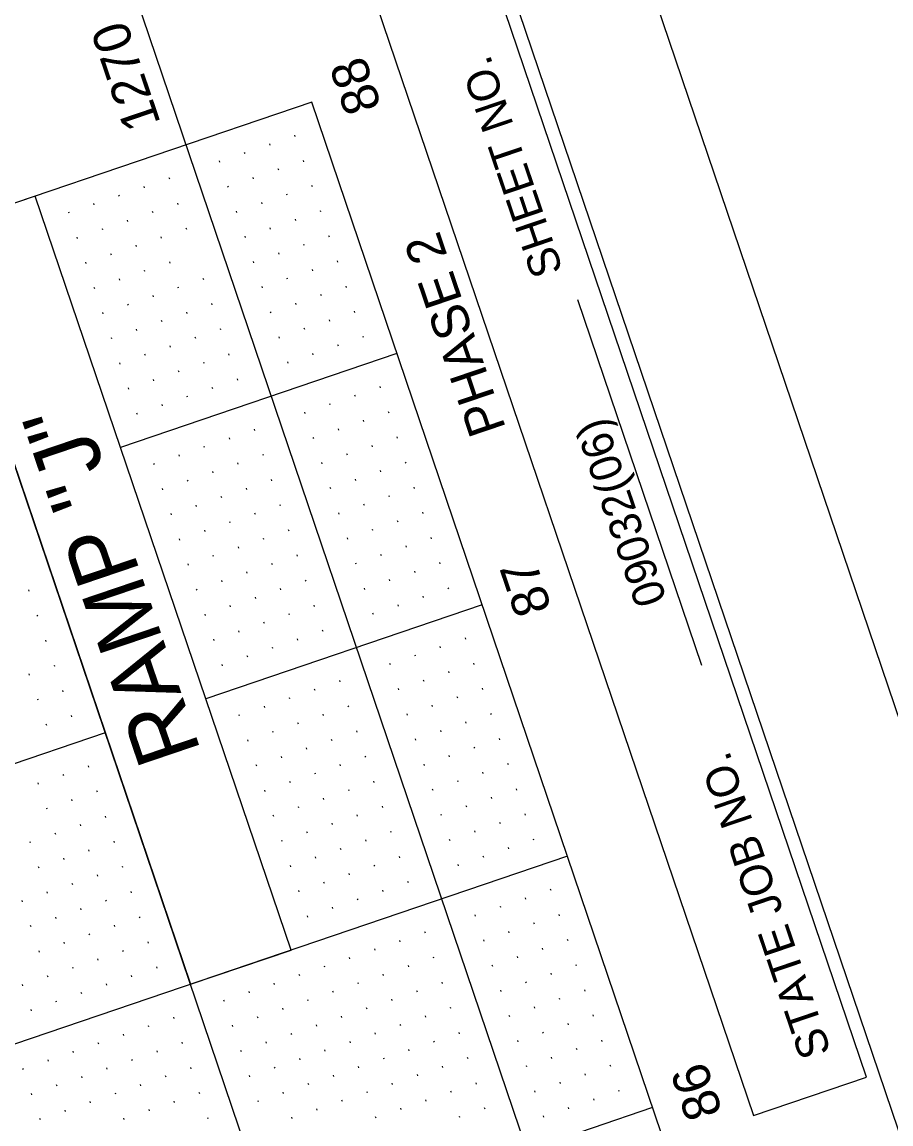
# Model space of a CAD drawing. Extents: x 2150800 to 2152547, y 141860 to 143950.
# Drawn here: x 2151789.3 to 2151953.1, y 143638.5 to 143846.1 of the extents above; entities that cross this region are included whole.
import ezdxf

# ---------------------------------------------------------------- set-up
doc = ezdxf.new("R2010")
doc.units = 0
for name, color, linetype in [('PR_Align_Ramp_J_Sta', 7, 'Continuous'), ('SHT_Plan_Profile_Sheet_Elev_Txt', 7, 'Continuous'), ('SHT_Plan_Profile_Sheet_Sta_Txt', 7, 'Continuous'), ('SHT_Plan_Profile_Sheet_Txt', 7, 'Continuous'), ('SHT_Plot_Shape_Half', 7, 'Continuous'), ('SHT_Profile_Grid_Major', 7, 'Continuous'), ('SHT_Profile_Grid_Minor', 7, 'Continuous'), ('SHT_Sheet_Border', 7, 'Continuous'), ('SHT_Standard_Sheet_Lines', 7, 'Continuous')]:
    doc.layers.add(name, color=color, linetype=linetype)

msp = doc.modelspace()

# ---------------------------------------------------------------- linework, layer by layer
at = {"layer": 'SHT_Plot_Shape_Half'}
msp.add_lwpolyline([(2151391.39, 141950.92), (2150845.24, 143560.8), (2151886.93, 143914.19), (2152433.08, 142304.31)], close=True, dxfattribs=at)
at = {"layer": 'SHT_Profile_Grid_Major'}
for p, q in [((2152314.16, 142366.92), (2151808.17, 143858.43)), ((2152266.81, 142350.86), (2151760.82, 143842.37)), ((2151859.95, 143783.6), (2151807.87, 143765.93)), ((2151876.02, 143736.25), (2151823.93, 143718.58)), ((2151804.99, 143712.16), (2151468.81, 143598.11)), ((2151892.08, 143688.9), (2151484.88, 143550.76)), ((2151908.14, 143641.55), (2151458.32, 143488.95))]:
    msp.add_line(p, q, dxfattribs=at)
at = {"layer": 'SHT_Profile_Grid_Minor'}
for p, q in [((2151840.8, 143824.49), (2151840.72, 143824.73)), ((2151836.07, 143822.88), (2151835.99, 143823.12)), ((2151831.33, 143821.28), (2151831.25, 143821.52)), ((2151826.6, 143819.67), (2151826.52, 143819.91)), ((2151842.41, 143819.76), (2151842.33, 143819.99)), ((2151817.13, 143816.46), (2151817.05, 143816.7)), ((2151832.94, 143816.54), (2151832.86, 143816.78)), ((2151837.67, 143818.15), (2151837.59, 143818.39)), ((2151812.39, 143814.85), (2151812.31, 143815.09)), ((2151828.2, 143814.94), (2151828.12, 143815.17)), ((2151844.02, 143815.02), (2151843.94, 143815.26)), ((2151807.66, 143813.25), (2151807.58, 143813.48)), ((2151839.28, 143813.42), (2151839.2, 143813.65)), ((2151798.19, 143810.03), (2151798.11, 143810.27)), ((2151802.92, 143811.64), (2151802.84, 143811.88)), ((2151814, 143810.12), (2151813.92, 143810.36)), ((2151818.73, 143811.72), (2151818.65, 143811.96)), ((2151829.81, 143810.2), (2151829.73, 143810.44)), ((2151834.55, 143811.81), (2151834.47, 143812.05)), ((2151845.62, 143810.29), (2151845.54, 143810.52)), ((2151809.26, 143808.51), (2151809.18, 143808.75)), ((2151840.89, 143808.68), (2151840.81, 143808.92)), ((2151804.53, 143806.91), (2151804.45, 143807.14)), ((2151820.34, 143806.99), (2151820.26, 143807.23)), ((2151836.15, 143807.07), (2151836.07, 143807.31)), ((2151799.79, 143805.3), (2151799.71, 143805.54)), ((2151810.87, 143803.78), (2151810.79, 143804.01)), ((2151815.61, 143805.38), (2151815.53, 143805.62)), ((2151831.42, 143805.47), (2151831.34, 143805.7)), ((2151842.49, 143803.95), (2151842.41, 143804.18)), ((2151847.23, 143805.55), (2151847.15, 143805.79)), ((2151806.14, 143802.17), (2151806.06, 143802.41)), ((2151837.76, 143802.34), (2151837.68, 143802.58)), ((2151801.4, 143800.56), (2151801.32, 143800.8)), ((2151817.21, 143800.65), (2151817.13, 143800.89)), ((2151833.02, 143800.73), (2151832.94, 143800.97)), ((2151848.83, 143800.82), (2151848.75, 143801.05)), ((2151812.48, 143799.04), (2151812.4, 143799.28)), ((2151823.55, 143797.52), (2151823.47, 143797.76)), ((2151839.36, 143797.6), (2151839.28, 143797.84)), ((2151844.1, 143799.21), (2151844.02, 143799.45)), ((2151803.01, 143795.83), (2151802.93, 143796.07)), ((2151807.74, 143797.44), (2151807.66, 143797.67)), ((2151818.82, 143795.91), (2151818.74, 143796.15)), ((2151834.63, 143796), (2151834.55, 143796.23)), ((2151850.44, 143796.08), (2151850.36, 143796.32)), ((2151814.08, 143794.31), (2151814, 143794.54)), ((2151845.71, 143794.48), (2151845.63, 143794.71)), ((2151809.35, 143792.7), (2151809.27, 143792.94)), ((2151825.16, 143792.78), (2151825.08, 143793.02)), ((2151836.24, 143791.26), (2151836.16, 143791.5)), ((2151840.97, 143792.87), (2151840.89, 143793.11)), ((2151852.05, 143791.35), (2151851.97, 143791.58)), ((2151804.61, 143791.09), (2151804.53, 143791.33)), ((2151815.69, 143789.57), (2151815.61, 143789.81)), ((2151820.42, 143791.18), (2151820.34, 143791.42)), ((2151847.31, 143789.74), (2151847.23, 143789.98)), ((2151810.96, 143787.97), (2151810.87, 143788.2)), ((2151826.77, 143788.05), (2151826.69, 143788.29)), ((2151842.58, 143788.13), (2151842.5, 143788.37)), ((2151806.22, 143786.36), (2151806.14, 143786.6)), ((2151822.03, 143786.44), (2151821.95, 143786.68)), ((2151837.84, 143786.53), (2151837.76, 143786.76)), ((2151853.65, 143786.61), (2151853.57, 143786.85)), ((2151812.56, 143783.23), (2151812.48, 143783.47)), ((2151817.3, 143784.84), (2151817.22, 143785.07)), ((2151828.37, 143783.32), (2151828.29, 143783.55)), ((2151844.18, 143783.4), (2151844.1, 143783.64)), ((2151848.92, 143785.01), (2151848.84, 143785.24)), ((2151807.83, 143781.62), (2151807.75, 143781.86)), ((2151823.64, 143781.71), (2151823.56, 143781.95)), ((2151839.45, 143781.79), (2151839.37, 143782.03)), ((2151818.9, 143780.1), (2151818.82, 143780.34)), ((2151809.43, 143776.89), (2151809.35, 143777.13)), ((2151814.17, 143778.5), (2151814.09, 143778.73)), ((2151825.24, 143776.97), (2151825.16, 143777.21)), ((2151829.98, 143778.58), (2151829.9, 143778.82)), ((2151856.87, 143777.14), (2151856.79, 143777.38)), ((2151820.51, 143775.37), (2151820.43, 143775.6)), ((2151852.13, 143775.54), (2151852.05, 143775.77)), ((2151815.77, 143773.76), (2151815.69, 143774)), ((2151847.4, 143773.93), (2151847.32, 143774.17)), ((2151811.04, 143772.15), (2151810.96, 143772.39)), ((2151842.66, 143772.32), (2151842.58, 143772.56)), ((2151853.74, 143770.8), (2151853.66, 143771.04)), ((2151858.47, 143772.41), (2151858.39, 143772.64)), ((2151833.19, 143769.11), (2151833.11, 143769.35)), ((2151849, 143769.19), (2151848.92, 143769.43)), ((2151828.46, 143767.5), (2151828.38, 143767.74)), ((2151844.27, 143767.59), (2151844.19, 143767.82)), ((2151860.08, 143767.67), (2151860, 143767.91)), ((2151818.99, 143764.29), (2151818.91, 143764.53)), ((2151823.72, 143765.9), (2151823.64, 143766.13)), ((2151834.8, 143764.38), (2151834.72, 143764.61)), ((2151850.61, 143764.46), (2151850.53, 143764.7)), ((2151855.34, 143766.07), (2151855.26, 143766.3)), ((2151814.25, 143762.68), (2151814.17, 143762.92)), ((2151830.06, 143762.77), (2151829.98, 143763.01)), ((2151845.87, 143762.85), (2151845.79, 143763.09)), ((2151861.69, 143762.94), (2151861.6, 143763.17)), ((2151825.33, 143761.16), (2151825.25, 143761.4)), ((2151856.95, 143761.33), (2151856.87, 143761.57)), ((2151820.59, 143759.56), (2151820.51, 143759.79)), ((2151836.4, 143759.64), (2151836.32, 143759.88)), ((2151847.48, 143758.12), (2151847.4, 143758.35)), ((2151852.22, 143759.72), (2151852.13, 143759.96)), ((2151863.29, 143758.2), (2151863.21, 143758.44)), ((2151815.86, 143757.95), (2151815.78, 143758.19)), ((2151826.93, 143756.43), (2151826.85, 143756.66)), ((2151831.67, 143758.03), (2151831.59, 143758.27)), ((2151858.56, 143756.6), (2151858.48, 143756.83)), ((2151822.2, 143754.82), (2151822.12, 143755.06)), ((2151838.01, 143754.91), (2151837.93, 143755.14)), ((2151853.82, 143754.99), (2151853.74, 143755.23)), ((2151817.46, 143753.22), (2151817.38, 143753.45)), ((2151833.28, 143753.3), (2151833.2, 143753.54)), ((2151849.09, 143753.38), (2151849.01, 143753.62)), ((2151860.16, 143751.86), (2151860.08, 143752.1)), ((2151864.9, 143753.47), (2151864.82, 143753.7)), ((2151823.81, 143750.09), (2151823.73, 143750.32)), ((2151828.54, 143751.69), (2151828.46, 143751.93)), ((2151839.62, 143750.17), (2151839.54, 143750.41)), ((2151855.43, 143750.25), (2151855.35, 143750.49)), ((2151819.07, 143748.48), (2151818.99, 143748.72)), ((2151834.88, 143748.56), (2151834.8, 143748.8)), ((2151850.69, 143748.65), (2151850.61, 143748.88)), ((2151866.5, 143748.73), (2151866.42, 143748.97)), ((2151830.15, 143746.96), (2151830.07, 143747.19)), ((2151861.77, 143747.13), (2151861.69, 143747.36)), ((2151820.68, 143743.75), (2151820.6, 143743.98)), ((2151825.41, 143745.35), (2151825.33, 143745.59)), ((2151836.49, 143743.83), (2151836.41, 143744.07)), ((2151841.22, 143745.44), (2151841.14, 143745.67)), ((2151852.3, 143743.91), (2151852.22, 143744.15)), ((2151857.03, 143745.52), (2151856.95, 143745.76)), ((2151868.11, 143744), (2151868.03, 143744.23)), ((2151831.75, 143742.22), (2151831.67, 143742.46)), ((2151863.38, 143742.39), (2151863.3, 143742.63)), ((2151827.02, 143740.62), (2151826.94, 143740.85)), ((2151842.83, 143740.7), (2151842.75, 143740.94)), ((2151858.64, 143740.78), (2151858.56, 143741.02)), ((2151790.66, 143738.84), (2151790.58, 143739.08)), ((2151822.28, 143739.01), (2151822.2, 143739.25)), ((2151833.36, 143737.49), (2151833.28, 143737.72)), ((2151838.09, 143739.09), (2151838.01, 143739.33)), ((2151853.91, 143739.18), (2151853.83, 143739.41)), ((2151864.98, 143737.66), (2151864.9, 143737.89)), ((2151869.72, 143739.26), (2151869.64, 143739.5)), ((2151828.62, 143735.88), (2151828.54, 143736.12)), ((2151844.44, 143735.97), (2151844.36, 143736.2)), ((2151860.25, 143736.05), (2151860.17, 143736.29)), ((2151792.27, 143734.11), (2151792.19, 143734.34)), ((2151823.89, 143734.28), (2151823.81, 143734.51)), ((2151839.7, 143734.36), (2151839.62, 143734.6)), ((2151855.51, 143734.44), (2151855.43, 143734.68)), ((2151830.23, 143731.15), (2151830.15, 143731.38)), ((2151834.97, 143732.75), (2151834.89, 143732.99)), ((2151846.04, 143731.23), (2151845.96, 143731.47)), ((2151793.87, 143729.37), (2151793.79, 143729.61)), ((2151825.5, 143729.54), (2151825.42, 143729.78)), ((2151841.31, 143729.62), (2151841.23, 143729.86)), ((2151872.93, 143729.79), (2151872.85, 143730.03)), ((2151836.57, 143728.02), (2151836.49, 143728.25)), ((2151868.19, 143728.19), (2151868.11, 143728.42)), ((2151831.84, 143726.41), (2151831.76, 143726.65)), ((2151858.72, 143724.97), (2151858.64, 143725.21)), ((2151863.46, 143726.58), (2151863.38, 143726.82)), ((2151874.54, 143725.06), (2151874.46, 143725.29)), ((2151790.74, 143723.03), (2151790.66, 143723.27)), ((2151795.48, 143724.64), (2151795.4, 143724.87)), ((2151827.1, 143724.81), (2151827.02, 143725.04)), ((2151869.8, 143723.45), (2151869.72, 143723.69)), ((2151849.25, 143721.76), (2151849.17, 143722)), ((2151865.07, 143721.84), (2151864.99, 143722.08)), ((2151797.09, 143719.9), (2151797.01, 143720.14)), ((2151844.52, 143720.15), (2151844.44, 143720.39)), ((2151860.33, 143720.24), (2151860.25, 143720.48)), ((2151871.41, 143718.72), (2151871.33, 143718.95)), ((2151876.14, 143720.32), (2151876.06, 143720.56)), ((2151792.35, 143718.3), (2151792.27, 143718.53)), ((2151835.05, 143716.94), (2151834.97, 143717.18)), ((2151839.78, 143718.55), (2151839.7, 143718.78)), ((2151850.86, 143717.03), (2151850.78, 143717.26)), ((2151866.67, 143717.11), (2151866.59, 143717.35)), ((2151798.69, 143715.17), (2151798.61, 143715.4)), ((2151830.31, 143715.34), (2151830.23, 143715.57)), ((2151846.13, 143715.42), (2151846.05, 143715.66)), ((2151861.94, 143715.5), (2151861.86, 143715.74)), ((2151877.75, 143715.59), (2151877.67, 143715.82)), ((2151793.96, 143713.56), (2151793.88, 143713.8)), ((2151841.39, 143713.81), (2151841.31, 143714.05)), ((2151868.28, 143712.37), (2151868.2, 143712.61)), ((2151873.01, 143713.98), (2151872.93, 143714.22)), ((2151831.92, 143710.6), (2151831.84, 143710.84)), ((2151836.66, 143712.21), (2151836.58, 143712.44)), ((2151847.73, 143710.68), (2151847.65, 143710.92)), ((2151852.47, 143712.29), (2151852.39, 143712.53)), ((2151863.54, 143710.77), (2151863.46, 143711.01)), ((2151879.35, 143710.85), (2151879.27, 143711.09)), ((2151843, 143709.08), (2151842.92, 143709.31)), ((2151874.62, 143709.25), (2151874.54, 143709.48)), ((2151838.26, 143707.47), (2151838.18, 143707.71)), ((2151854.07, 143707.56), (2151853.99, 143707.79)), ((2151869.88, 143707.64), (2151869.8, 143707.88)), ((2151797.17, 143704.09), (2151797.09, 143704.33)), ((2151801.91, 143705.7), (2151801.82, 143705.93)), ((2151833.53, 143705.87), (2151833.45, 143706.1)), ((2151844.6, 143704.34), (2151844.52, 143704.58)), ((2151849.34, 143705.95), (2151849.26, 143706.19)), ((2151865.15, 143706.03), (2151865.07, 143706.27)), ((2151876.23, 143704.51), (2151876.15, 143704.75)), ((2151880.96, 143706.12), (2151880.88, 143706.35)), ((2151792.44, 143702.48), (2151792.35, 143702.72)), ((2151839.87, 143702.74), (2151839.79, 143702.97)), ((2151855.68, 143702.82), (2151855.6, 143703.06)), ((2151871.49, 143702.9), (2151871.41, 143703.14)), ((2151803.51, 143700.96), (2151803.43, 143701.2)), ((2151835.13, 143701.13), (2151835.05, 143701.37)), ((2151850.94, 143701.21), (2151850.86, 143701.45)), ((2151866.76, 143701.3), (2151866.68, 143701.54)), ((2151882.57, 143701.38), (2151882.49, 143701.62)), ((2151798.78, 143699.36), (2151798.7, 143699.59)), ((2151841.48, 143698), (2151841.39, 143698.24)), ((2151846.21, 143699.61), (2151846.13, 143699.85)), ((2151857.29, 143698.09), (2151857.21, 143698.32)), ((2151873.1, 143698.17), (2151873.02, 143698.41)), ((2151877.83, 143699.78), (2151877.75, 143700.01)), ((2151794.04, 143697.75), (2151793.96, 143697.99)), ((2151805.12, 143696.23), (2151805.04, 143696.46)), ((2151836.74, 143696.4), (2151836.66, 143696.63)), ((2151852.55, 143696.48), (2151852.47, 143696.72)), ((2151868.36, 143696.56), (2151868.28, 143696.8)), ((2151884.17, 143696.65), (2151884.09, 143696.88)), ((2151800.38, 143694.62), (2151800.3, 143694.86)), ((2151847.82, 143694.87), (2151847.74, 143695.11)), ((2151879.44, 143695.04), (2151879.36, 143695.28)), ((2151795.65, 143693.01), (2151795.57, 143693.25)), ((2151838.35, 143691.66), (2151838.27, 143691.9)), ((2151843.08, 143693.27), (2151843, 143693.5)), ((2151854.16, 143691.74), (2151854.08, 143691.98)), ((2151858.89, 143693.35), (2151858.81, 143693.59)), ((2151869.97, 143691.83), (2151869.89, 143692.07)), ((2151874.7, 143693.44), (2151874.62, 143693.67)), ((2151885.78, 143691.91), (2151885.7, 143692.15)), ((2151790.91, 143691.41), (2151790.83, 143691.65)), ((2151801.99, 143689.89), (2151801.91, 143690.12)), ((2151806.72, 143691.49), (2151806.64, 143691.73)), ((2151849.42, 143690.14), (2151849.34, 143690.38)), ((2151881.04, 143690.31), (2151880.96, 143690.54)), ((2151797.25, 143688.28), (2151797.17, 143688.52)), ((2151844.69, 143688.53), (2151844.61, 143688.77)), ((2151860.5, 143688.62), (2151860.42, 143688.85)), ((2151876.31, 143688.7), (2151876.23, 143688.94)), ((2151792.52, 143686.67), (2151792.44, 143686.91)), ((2151808.33, 143686.76), (2151808.25, 143686.99)), ((2151839.95, 143686.93), (2151839.87, 143687.16)), ((2151851.03, 143685.4), (2151850.95, 143685.64)), ((2151855.76, 143687.01), (2151855.68, 143687.25)), ((2151871.58, 143687.09), (2151871.49, 143687.33)), ((2151798.86, 143683.55), (2151798.78, 143683.78)), ((2151803.6, 143685.15), (2151803.52, 143685.39)), ((2151846.29, 143683.8), (2151846.21, 143684.03)), ((2151862.11, 143683.88), (2151862.02, 143684.12)), ((2151794.13, 143681.94), (2151794.05, 143682.18)), ((2151809.94, 143682.02), (2151809.86, 143682.26)), ((2151841.56, 143682.19), (2151841.48, 143682.43)), ((2151857.37, 143682.27), (2151857.29, 143682.51)), ((2151888.99, 143682.44), (2151888.91, 143682.68)), ((2151789.39, 143680.33), (2151789.31, 143680.57)), ((2151805.2, 143680.42), (2151805.12, 143680.65)), ((2151852.64, 143680.67), (2151852.55, 143680.91)), ((2151879.52, 143679.23), (2151879.44, 143679.47)), ((2151884.26, 143680.84), (2151884.18, 143681.07)), ((2151795.73, 143677.2), (2151795.65, 143677.44)), ((2151800.47, 143678.81), (2151800.39, 143679.05)), ((2151811.54, 143677.29), (2151811.46, 143677.52)), ((2151843.17, 143677.46), (2151843.09, 143677.69)), ((2151847.9, 143679.06), (2151847.82, 143679.3)), ((2151874.79, 143677.62), (2151874.71, 143677.86)), ((2151890.6, 143677.71), (2151890.52, 143677.94)), ((2151791, 143675.6), (2151790.92, 143675.83)), ((2151806.81, 143675.68), (2151806.73, 143675.92)), ((2151885.86, 143676.1), (2151885.78, 143676.34)), ((2151802.07, 143674.08), (2151801.99, 143674.31)), ((2151865.32, 143674.41), (2151865.24, 143674.65)), ((2151881.13, 143674.5), (2151881.05, 143674.73)), ((2151892.21, 143672.97), (2151892.12, 143673.21)), ((2151792.6, 143670.86), (2151792.52, 143671.1)), ((2151797.34, 143672.47), (2151797.26, 143672.71)), ((2151808.41, 143670.95), (2151808.33, 143671.18)), ((2151813.15, 143672.55), (2151813.07, 143672.79)), ((2151855.85, 143671.2), (2151855.77, 143671.44)), ((2151860.58, 143672.8), (2151860.5, 143673.04)), ((2151876.39, 143672.89), (2151876.31, 143673.13)), ((2151887.47, 143671.37), (2151887.39, 143671.6)), ((2151803.68, 143669.34), (2151803.6, 143669.58)), ((2151851.11, 143669.59), (2151851.03, 143669.83)), ((2151866.92, 143669.68), (2151866.84, 143669.91)), ((2151882.74, 143669.76), (2151882.66, 143670)), ((2151798.94, 143667.73), (2151798.86, 143667.97)), ((2151814.76, 143667.82), (2151814.68, 143668.05)), ((2151846.38, 143667.99), (2151846.3, 143668.22)), ((2151862.19, 143668.07), (2151862.11, 143668.31)), ((2151878, 143668.15), (2151877.92, 143668.39)), ((2151893.81, 143668.24), (2151893.73, 143668.47)), ((2151794.21, 143666.13), (2151794.13, 143666.36)), ((2151810.02, 143666.21), (2151809.94, 143666.45)), ((2151836.91, 143664.77), (2151836.83, 143665.01)), ((2151841.64, 143666.38), (2151841.56, 143666.62)), ((2151852.72, 143664.86), (2151852.64, 143665.09)), ((2151857.45, 143666.46), (2151857.37, 143666.7)), ((2151868.53, 143664.94), (2151868.45, 143665.18)), ((2151884.34, 143665.03), (2151884.26, 143665.26)), ((2151889.08, 143666.63), (2151889, 143666.87)), ((2151789.47, 143664.52), (2151789.39, 143664.76)), ((2151800.55, 143663), (2151800.47, 143663.24)), ((2151805.29, 143664.61), (2151805.21, 143664.84)), ((2151832.17, 143663.17), (2151832.09, 143663.4)), ((2151847.98, 143663.25), (2151847.9, 143663.49)), ((2151863.8, 143663.33), (2151863.72, 143663.57)), ((2151879.61, 143663.42), (2151879.53, 143663.66)), ((2151895.42, 143663.5), (2151895.34, 143663.74)), ((2151795.82, 143661.39), (2151795.74, 143661.63)), ((2151827.44, 143661.56), (2151827.36, 143661.8)), ((2151843.25, 143661.64), (2151843.17, 143661.88)), ((2151859.06, 143661.73), (2151858.98, 143661.97)), ((2151890.68, 143661.9), (2151890.6, 143662.13)), ((2151791.08, 143659.79), (2151791, 143660.02)), ((2151833.78, 143658.43), (2151833.7, 143658.67)), ((2151838.51, 143660.04), (2151838.43, 143660.28)), ((2151849.59, 143658.52), (2151849.51, 143658.75)), ((2151854.33, 143660.12), (2151854.25, 143660.36)), ((2151865.4, 143658.6), (2151865.32, 143658.84)), ((2151870.14, 143660.21), (2151870.06, 143660.44)), ((2151881.21, 143658.68), (2151881.13, 143658.92)), ((2151885.95, 143660.29), (2151885.87, 143660.53)), ((2151897.02, 143658.77), (2151896.94, 143659)), ((2151813.23, 143656.74), (2151813.15, 143656.98)), ((2151817.97, 143658.35), (2151817.89, 143658.58)), ((2151829.04, 143656.83), (2151828.96, 143657.06)), ((2151844.86, 143656.91), (2151844.78, 143657.15)), ((2151860.67, 143656.99), (2151860.59, 143657.23)), ((2151892.29, 143657.16), (2151892.21, 143657.4)), ((2151808.5, 143655.14), (2151808.42, 143655.37)), ((2151840.12, 143655.3), (2151840.04, 143655.54)), ((2151855.93, 143655.39), (2151855.85, 143655.62)), ((2151871.74, 143655.47), (2151871.66, 143655.71)), ((2151887.55, 143655.56), (2151887.47, 143655.79)), ((2151803.76, 143653.53), (2151803.68, 143653.77)), ((2151819.57, 143653.61), (2151819.49, 143653.85)), ((2151835.39, 143653.7), (2151835.31, 143653.93)), ((2151846.46, 143652.17), (2151846.38, 143652.41)), ((2151851.2, 143653.78), (2151851.12, 143654.02)), ((2151862.27, 143652.26), (2151862.19, 143652.5)), ((2151867.01, 143653.87), (2151866.93, 143654.1)), ((2151882.82, 143653.95), (2151882.74, 143654.19)), ((2151893.9, 143652.43), (2151893.82, 143652.66)), ((2151898.63, 143654.03), (2151898.55, 143654.27)), ((2151794.29, 143650.32), (2151794.21, 143650.55)), ((2151799.03, 143651.92), (2151798.95, 143652.16)), ((2151810.1, 143650.4), (2151810.02, 143650.64)), ((2151814.84, 143652.01), (2151814.76, 143652.24)), ((2151830.65, 143652.09), (2151830.57, 143652.33)), ((2151841.73, 143650.57), (2151841.65, 143650.81)), ((2151857.54, 143650.65), (2151857.46, 143650.89)), ((2151873.35, 143650.74), (2151873.27, 143650.97)), ((2151889.16, 143650.82), (2151889.08, 143651.06)), ((2151789.56, 143648.71), (2151789.48, 143648.95)), ((2151805.37, 143648.79), (2151805.29, 143649.03)), ((2151821.18, 143648.88), (2151821.1, 143649.11)), ((2151836.99, 143648.96), (2151836.91, 143649.2)), ((2151852.8, 143649.05), (2151852.72, 143649.28)), ((2151868.61, 143649.13), (2151868.53, 143649.37)), ((2151884.43, 143649.21), (2151884.35, 143649.45)), ((2151900.24, 143649.3), (2151900.16, 143649.53)), ((2151800.63, 143647.19), (2151800.55, 143647.42)), ((2151816.45, 143647.27), (2151816.37, 143647.51)), ((2151832.26, 143647.36), (2151832.18, 143647.59)), ((2151848.07, 143647.44), (2151847.99, 143647.68)), ((2151863.88, 143647.52), (2151863.8, 143647.76)), ((2151874.96, 143646), (2151874.88, 143646.24)), ((2151890.77, 143646.09), (2151890.69, 143646.32)), ((2151895.5, 143647.69), (2151895.42, 143647.93)), ((2151791.16, 143643.98), (2151791.08, 143644.21)), ((2151795.9, 143645.58), (2151795.82, 143645.82)), ((2151806.98, 143644.06), (2151806.9, 143644.3)), ((2151811.71, 143645.67), (2151811.63, 143645.9)), ((2151822.79, 143644.14), (2151822.71, 143644.38)), ((2151838.6, 143644.23), (2151838.52, 143644.46)), ((2151843.33, 143645.83), (2151843.25, 143646.07)), ((2151854.41, 143644.31), (2151854.33, 143644.55)), ((2151859.14, 143645.92), (2151859.06, 143646.15)), ((2151870.22, 143644.4), (2151870.14, 143644.63)), ((2151886.03, 143644.48), (2151885.95, 143644.72)), ((2151901.84, 143644.56), (2151901.76, 143644.8)), ((2151802.24, 143642.45), (2151802.16, 143642.69)), ((2151818.05, 143642.54), (2151817.97, 143642.77)), ((2151833.86, 143642.62), (2151833.78, 143642.86)), ((2151849.67, 143642.7), (2151849.59, 143642.94)), ((2151865.49, 143642.79), (2151865.41, 143643.03)), ((2151897.11, 143642.96), (2151897.03, 143643.19)), ((2151797.51, 143640.85), (2151797.43, 143641.08)), ((2151813.32, 143640.93), (2151813.24, 143641.17)), ((2151844.94, 143641.1), (2151844.86, 143641.34)), ((2151860.75, 143641.18), (2151860.67, 143641.42)), ((2151876.56, 143641.27), (2151876.48, 143641.5)), ((2151887.64, 143639.74), (2151887.56, 143639.98)), ((2151892.37, 143641.35), (2151892.29, 143641.59)), ((2151792.77, 143639.24), (2151792.69, 143639.48)), ((2151808.58, 143639.32), (2151808.5, 143639.56)), ((2151824.39, 143639.41), (2151824.31, 143639.64)), ((2151840.2, 143639.49), (2151840.12, 143639.73)), ((2151856.02, 143639.58), (2151855.94, 143639.81)), ((2151871.83, 143639.66), (2151871.75, 143639.9))]:
    msp.add_line(p, q, dxfattribs=at)
at = {"layer": 'SHT_Sheet_Border'}
msp.add_line((2151843.89, 143830.95), (2151394.07, 143678.35), dxfattribs=at)
for points in [[(2151383.74, 142051.28), (2150877.75, 143542.79), (2151872.09, 143880.12), (2152378.08, 142388.61)], [(2151927.13, 143640.07), (2151948.43, 143647.3), (2151870.53, 143876.95), (2151849.22, 143869.72)], [(2151821.06, 143664.81), (2151840, 143671.23), (2151791.81, 143813.28), (2151772.87, 143806.86)]]:
    msp.add_lwpolyline(points, close=True, dxfattribs=at)
msp.add_lwpolyline([(2151939.85, 143625.91), (2151916.18, 143617.88), (2151843.89, 143830.95)], dxfattribs=at)
at = {"layer": 'SHT_Standard_Sheet_Lines'}
msp.add_line((2151917.43, 143724.87), (2151894.07, 143793.73), dxfattribs=at)

# ---------------------------------------------------------------- texts
at = {"layer": 'PR_Align_Ramp_J_Sta'}
msp.add_text('RAMP "J"', height=12, rotation=108.7393, dxfattribs=at).set_placement((2151823.08, 143708.66))
at = {"layer": 'SHT_Plan_Profile_Sheet_Elev_Txt'}
msp.add_text('1270', height=7, rotation=108.7393, dxfattribs=at).set_placement((2151815.49, 143827.01))
at = {"layer": 'SHT_Plan_Profile_Sheet_Sta_Txt'}
for s, p in [('88', (2151857.1, 143830.15)), ('87', (2151889.18, 143735.58)), ('86', (2151921.38, 143640.66))]:
    msp.add_text(s, height=7, rotation=108.7393, dxfattribs=at).set_placement(p)
at = {"layer": 'SHT_Plan_Profile_Sheet_Txt'}
for s, height, p in [('SHEET NO.', 6, (2151891.3, 143799.2)), ('PHASE 2', 7, (2151880.54, 143769.51)), ('09032(06)', 6, (2151910.86, 143737.23)), ('STATE JOB NO.', 6, (2151941.82, 143652.03))]:
    msp.add_text(s, height=height, rotation=108.7393, dxfattribs=at).set_placement(p)

doc.saveas('drawing.dxf')
